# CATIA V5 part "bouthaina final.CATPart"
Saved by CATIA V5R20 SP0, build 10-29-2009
Part number: porte
Bounding box of the stored display mesh (mm): x -40 to 0, y 0 to 270, z 0 to 360
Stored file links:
  C:\Users\bensf\Desktop\bouthaina\bouthaina final.CATPart
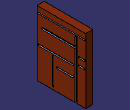
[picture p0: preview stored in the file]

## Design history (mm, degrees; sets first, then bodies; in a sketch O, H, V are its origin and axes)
Body1 (main body)
  Sketch1 on yz-plane, origin (0, 0, 0), H (0, 1, 0), V (0, 0, 1)
    line L1 (0, 0) -> (270, 0)
    line L2 (270, 0) -> (270, 360)
    line L3 (270, 360) -> (0, 360)
    line L4 (0, 360) -> (0, 0)
    length L4 = 360
    length L1 = 270
    horizontal: L1 H, L3 H
    vertical: L2 V, L4 V
  Pad1: profile Sketch1, direction (-1, 0, 0), length 40
  Sketch2 on start face of Pad1, origin (0, 0, 0), H (0, 1, 0), V (0, 0, 1)
    line L1 (266.9646, 330.1274) -> (0, 330.1274)
    line L2 (0, 330.1274) -> (0, 324.2682)
    line L3 (0, 324.2682) -> (266.9646, 324.2682)
    line L4 (266.9646, 324.2682) -> (266.9646, 330.1274)
    point P3 (0, 324.2682)
    line L5 (210.4215, 319.06) -> (223.4199, 319.06)
    line L6 (223.4199, 319.06) -> (223.4199, 0)
    line L7 (223.4199, 0) -> (210.4215, 0)
    line L8 (210.4215, 0) -> (210.4215, 319.06)
    point P7 (223.4199, 0)
    line L9 (27.1437, 270.2335) -> (210.4215, 270.2335)
    line L10 (210.4215, 270.2335) -> (210.4215, 259.1661)
    line L11 (210.4215, 259.1661) -> (27.1437, 259.1661)
    line L12 (27.1437, 259.1661) -> (27.1437, 270.2335)
    point P11 (210.4215, 259.1661)
    line L13 (228.6193, 231.1722) -> (266.9646, 231.1722)
    line L14 (266.9646, 231.1722) -> (266.9646, 223.3599)
    line L15 (266.9646, 223.3599) -> (228.6193, 223.3599)
    line L16 (228.6193, 223.3599) -> (228.6193, 231.1722)
    point P15 (266.9646, 223.3599)
    point P17 (228.6193, 190.8089)
    line L17 (228.6193, 190.8089) -> (266.9646, 190.8089)
    line L18 (266.9646, 190.8089) -> (266.9646, 183.6476)
    line L19 (266.9646, 183.6476) -> (228.6193, 183.6476)
    line L20 (228.6193, 183.6476) -> (228.6193, 190.8089)
    point P19 (266.9646, 183.6476)
    line L21 (200.6727, 179.7415) -> (3.7465, 179.7415)
    line L22 (3.7465, 179.7415) -> (3.7465, 171.2782)
    line L23 (3.7465, 171.2782) -> (200.6727, 171.2782)
    line L24 (200.6727, 171.2782) -> (200.6727, 179.7415)
    line L25 (84.3368, 165.419) -> (92.7857, 165.419)
    line L26 (92.7857, 165.419) -> (92.7857, 15.0332)
    line L27 (92.7857, 15.0332) -> (84.3368, 15.0332)
    line L28 (84.3368, 15.0332) -> (84.3368, 165.419)
    line L29 (107.7339, 120.4986) -> (200.6727, 120.4986)
    line L30 (200.6727, 120.4986) -> (200.6727, 112.6863)
    line L31 (200.6727, 112.6863) -> (107.7339, 112.6863)
    line L32 (107.7339, 112.6863) -> (107.7339, 120.4986)
    point P31 (200.6727, 112.6863)
    horizontal: L1 H, L3 H, L5 H, L7 H, L9 H, L11 H, L13 H, L15 H, L17 H, L19 H, L21 H, L23 H, L25 H, L27 H, L29 H, L31 H
    vertical: L2 V, L4 V, L6 V, L8 V, L10 V, L12 V, L14 V, L16 V, L18 V, L20 V, L22 V, L24 V, L26 V, L28 V, L30 V, L32 V
    coincidence: P3 V, P7 H, P11 L8, P15 L4, P17 L16, P19 L4, P31 L24
  Pocket1: profile Sketch2, direction (-1, 0, 0), length 7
